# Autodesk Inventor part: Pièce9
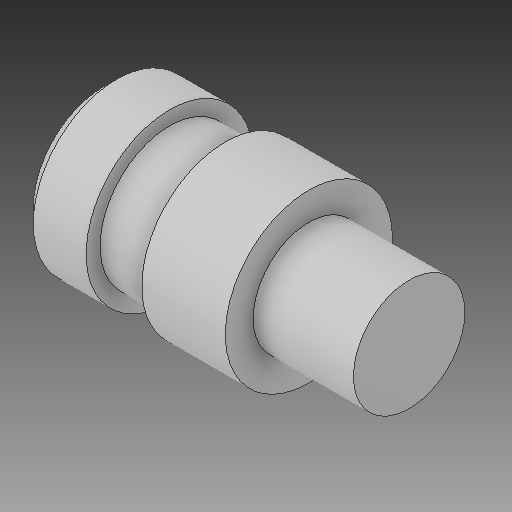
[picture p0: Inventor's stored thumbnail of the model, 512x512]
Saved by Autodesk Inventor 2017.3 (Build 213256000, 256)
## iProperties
Created: 2007-11
Part Number: Pièce9
Material: Générique
Document SubType Name: Modeling
Designer: ficho
Density: 1 g/cm^3
Appearance: Par défaut
Author: ficho
Sending System: SolidWorks 2009
Last Author: christophe
Last Saved: 2011-02-10
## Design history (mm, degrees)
feature "Chanfrein1"
node "Solide1"
